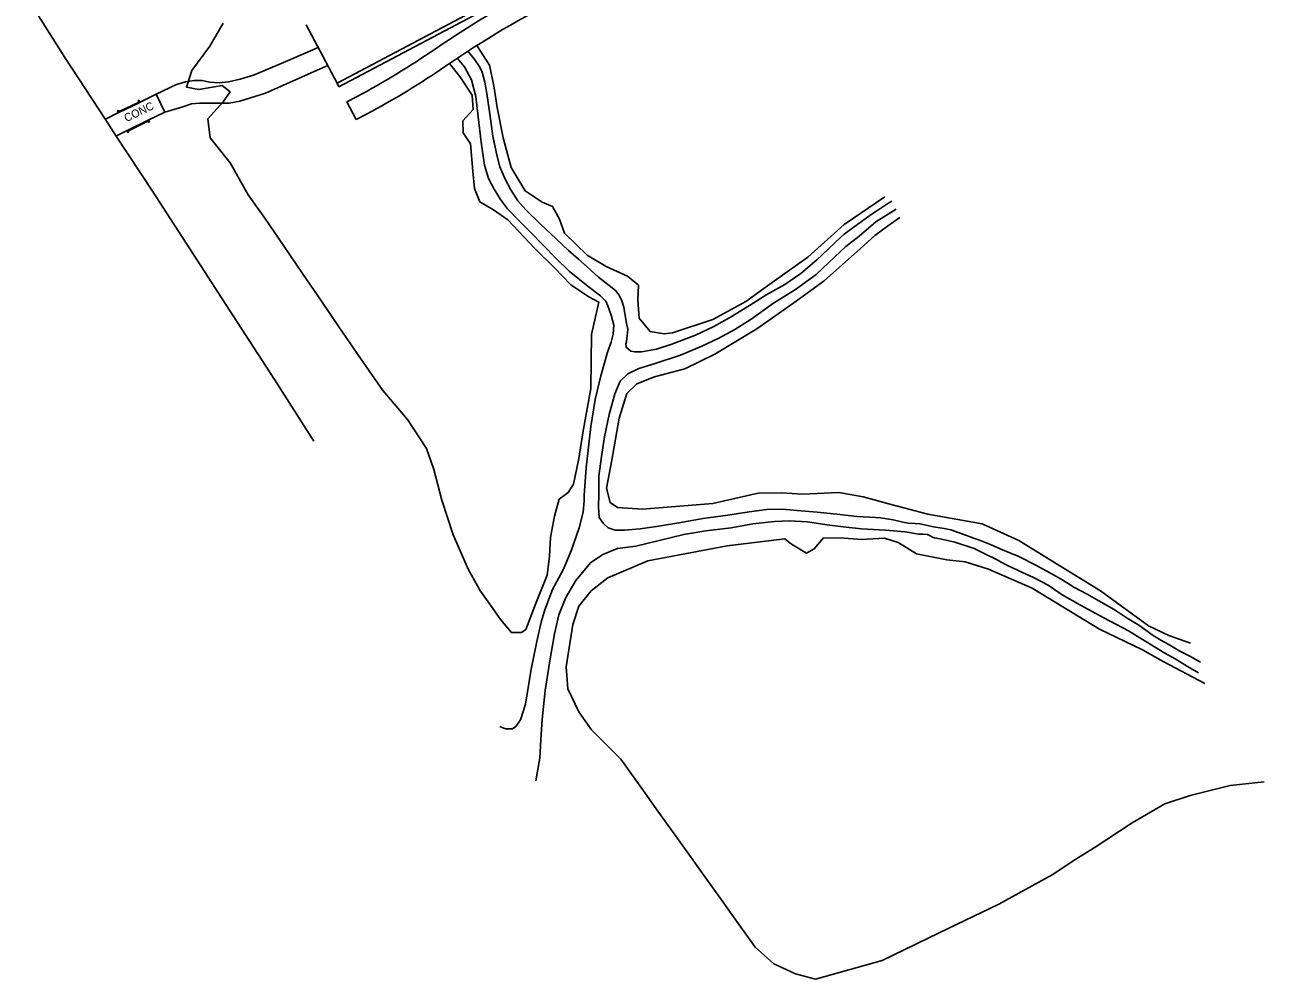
# Model space of a CAD drawing. Extents: x 1487693 to 1489338, y 497936 to 499734.
# Drawn here: x 1487693 to 1488313, y 497936 to 498412 of the extents above; entities that cross this region are included whole.
import ezdxf

# ---------------------------------------------------------------- set-up
doc = ezdxf.new("R2010")
doc.units = 0
for name, color, linetype in [('Exist Roads Curbs', 7, 'Continuous'), ('Exist Roads EOP', 7, 'Continuous'), ('Exist Roads EOP Other', 7, 'Continuous'), ('Exist Roads EOP Other Text', 7, 'Continuous'), ('Exist Roads Soil', 7, 'Continuous'), ('Exist Vegetation Woods Line', 7, 'Continuous'), ('Prop Conc 2ft 6in Curb and Gutter', 7, 'Continuous'), ('Prop Conc 4in Sidewalk', 7, 'Continuous'), ('Prop EOT', 7, 'Continuous')]:
    doc.layers.add(name, color=color, linetype=linetype)

msp = doc.modelspace()

# ---------------------------------------------------------------- linework, layer by layer
at = {"layer": 'Exist Roads Curbs'}
for points in [[(1487739.76, 498368.93), (1487740.04, 498369.54), (1487740.99, 498369.16), (1487750.11, 498373.59), (1487750.29, 498374.61), (1487750.83, 498374.37)], [(1487750.83, 498374.37), (1487750.59, 498373.38), (1487740.74, 498368.65), (1487739.76, 498368.93)], [(1487744.7, 498358.81), (1487745.13, 498359.75), (1487754.78, 498364.52), (1487755.85, 498364.17)], [(1487744.7, 498358.81), (1487745.23, 498358.62), (1487745.58, 498359.57), (1487754.62, 498363.96), (1487755.54, 498363.72), (1487755.85, 498364.17)]]:
    msp.add_lwpolyline(points, dxfattribs=at)
at = {"layer": 'Exist Roads EOP'}
for points in [[(1487693.5, 498427.87), (1487713.44, 498396.03), (1487733.84, 498365.05), (1487739.1, 498356.78), (1487757.33, 498329.19), (1487777.82, 498297.68)], [(1487759.21, 498377.68), (1487769.37, 498382.59), (1487773.83, 498383.92), (1487778.1, 498384.53), (1487781.97, 498384.53), (1487785.98, 498383.73), (1487790.67, 498383.41), (1487795.21, 498383.92), (1487801.16, 498385.18), (1487807.72, 498387.24), (1487820.37, 498392.44), (1487833.66, 498398.18), (1487840.07, 498401.02)], [(1487763.48, 498368.78), (1487772.46, 498371.42), (1487776.78, 498372.92), (1487780.8, 498373.14), (1487789.84, 498373.13), (1487795.58, 498373.12), (1487800.95, 498374.24), (1487813.75, 498378.14), (1487824.23, 498382.87), (1487838.14, 498388.98), (1487844.87, 498391.96)], [(1487777.82, 498297.68), (1487797.58, 498266.94), (1487818.25, 498235.23), (1487837.85, 498204.4)]]:
    msp.add_lwpolyline(points, dxfattribs=at)
at = {"layer": 'Exist Roads EOP Other'}
for points in [[(1487733.85, 498365.13), (1487740.73, 498368.64), (1487741.18, 498368.83), (1487750.54, 498373.36), (1487759.21, 498377.68), (1487763.48, 498368.78)], [(1487739.27, 498356.86), (1487744.95, 498359.66), (1487745.34, 498359.88), (1487754.86, 498364.57), (1487763.48, 498368.78)]]:
    msp.add_lwpolyline(points, dxfattribs=at)
at = {"layer": 'Exist Roads Soil'}
for points in [[(1487992.8, 498271.25), (1487991.79, 498274.42), (1487990.47, 498277.39), (1487988.71, 498279.71), (1487985.48, 498282.18), (1487980.22, 498286.24), (1487974.53, 498291.47), (1487970.09, 498295.27), (1487965.24, 498299.7), (1487958.99, 498305.49), (1487951.21, 498312.84), (1487943.9, 498319.95), (1487939.83, 498324.48), (1487936.37, 498329.99), (1487933.45, 498335.16), (1487930.78, 498341.35), (1487929.48, 498346.53), (1487927.32, 498356.65), (1487925.85, 498367.83), (1487924.38, 498377.95), (1487923.32, 498383.7), (1487922.02, 498388.61), (1487920.79, 498391.21), (1487918.11, 498395.39), (1487914.9, 498399.13)], [(1487981.4, 498237.08), (1487984.68, 498248.79), (1487986.53, 498253.92), (1487987.54, 498257.82), (1487987.79, 498262.28), (1487986.41, 498267.4), (1487984.8, 498272.03), (1487983.75, 498274.28), (1487981.23, 498276.93), (1487974.99, 498281.72), (1487965.45, 498289.32), (1487958.76, 498295.78), (1487952.42, 498302.4), (1487946.53, 498308.36), (1487940.29, 498314.61), (1487934.63, 498320.47), (1487931.21, 498325.07), (1487927.95, 498330.29), (1487925.23, 498335.58), (1487923.14, 498342.25), (1487921.46, 498353.8), (1487919.97, 498366.34), (1487918.8, 498376.58), (1487916.64, 498384.85), (1487913.27, 498391.29), (1487909.56, 498395.6)], [(1487998.13, 498248.94), (1488001.58, 498248.99), (1488009.14, 498250.29), (1488016.85, 498252.88), (1488028.57, 498257.26), (1488037.84, 498261.6), (1488046.16, 498266.36), (1488055.63, 498272.17), (1488064.34, 498277.72), (1488073.26, 498282.6), (1488081.19, 498288.09), (1488089.22, 498294.9), (1488094.75, 498300.05), (1488098.76, 498303.92), (1488102.94, 498307.7), (1488109.74, 498312.85), (1488115.28, 498316.73), (1488124.26, 498322.7), (1488126.64, 498324.22)], [(1488128.88, 498320.19), (1488118.78, 498313.96), (1488110.45, 498306.8), (1488103.79, 498301.57), (1488098.18, 498296.45), (1488088.95, 498287.56), (1488078.59, 498280.08), (1488067.61, 498273.26), (1488056.39, 498265.36), (1488048.22, 498260.11), (1488040.24, 498255.76), (1488031.77, 498251.78), (1488021.09, 498247.35), (1488008.48, 498243.18), (1488000.25, 498240.68), (1487994.75, 498238.1), (1487991.03, 498234.35), (1487988.26, 498228.05), (1487985.45, 498217.69), (1487983.17, 498206.59), (1487981.71, 498196.71), (1487980.28, 498186.98), (1487980.33, 498178.13), (1487980.09, 498171.36), (1487980.57, 498166.29), (1487982.53, 498163.44), (1487984.94, 498161.13), (1487988.49, 498159.91), (1487993.12, 498159.93), (1488000.97, 498160.56), (1488009.07, 498161.79), (1488020.32, 498163.6), (1488032.44, 498165.77), (1488044.75, 498167.41), (1488055.47, 498169.06), (1488064.34, 498170.27), (1488072.14, 498170.45), (1488079.38, 498169.79), (1488089.49, 498168.94), (1488099.18, 498168), (1488109.23, 498166.86), (1488115.53, 498166.46), (1488118.49, 498166.21), (1488121.02, 498166.1), (1488127.46, 498165.11), (1488132.18, 498164.02), (1488134.8, 498163.52), (1488138.41, 498163.27), (1488140.78, 498163.12), (1488147.6, 498161.61), (1488152.81, 498160.72), (1488156.15, 498160.1), (1488160.3, 498158.65), (1488165.94, 498156.63), (1488168.09, 498155.77), (1488170.57, 498154.9), (1488176.41, 498152.62), (1488182.09, 498150.21), (1488190.18, 498146.84), (1488198.63, 498142.47), (1488207.44, 498137.61), (1488212.24, 498135.04), (1488217.7, 498131.46), (1488224.25, 498128.05), (1488230.17, 498124.59), (1488237.75, 498120.28), (1488244.23, 498116.01), (1488248.54, 498113.48), (1488250.63, 498112.19), (1488257.33, 498107.35), (1488261.13, 498105.08), (1488264.84, 498102.98), (1488270.58, 498099.5), (1488275.24, 498097.13), (1488281, 498093.95)], [(1487998.13, 498248.94), (1487996.28, 498249.4), (1487993.94, 498251.33), (1487993.82, 498253.04), (1487994.13, 498254.17), (1487994.55, 498256.95), (1487994.74, 498260.33), (1487994.19, 498263.22), (1487992.8, 498271.25)], [(1487930.86, 498061.83), (1487933.61, 498060.75), (1487937.16, 498060.78), (1487938.89, 498061.96), (1487941.24, 498065.21), (1487943.61, 498073.08), (1487946.58, 498090.52), (1487949.33, 498104.43), (1487951.55, 498114.01), (1487953.34, 498120.24), (1487957.22, 498130.27), (1487962.55, 498140.15), (1487966.42, 498149.59), (1487970.53, 498161.2), (1487972.42, 498169), (1487972.97, 498174.6), (1487973.01, 498177.37), (1487974.01, 498191.07), (1487976.34, 498211.69), (1487978.41, 498225.2), (1487981.4, 498237.08)], [(1487948.87, 498034.82), (1487949.61, 498039.57), (1487950.84, 498046.04), (1487951.42, 498055.42), (1487951.96, 498065.46), (1487953.53, 498079.87), (1487955.89, 498094.73), (1487958.23, 498108.17), (1487960.34, 498117.7), (1487963.77, 498126.34), (1487968.76, 498134.78), (1487976.11, 498143.71), (1487982.38, 498147.83), (1487989.65, 498150.75), (1487998.84, 498151.97), (1488010.44, 498154.8), (1488022.73, 498157.84), (1488033.8, 498159.64), (1488046.43, 498161.09), (1488057.27, 498163.18), (1488068.04, 498164.33), (1488075.4, 498164.65), (1488084.57, 498164.05), (1488094.43, 498162.54), (1488102.43, 498161.54), (1488111.6, 498160.68), (1488123.53, 498159.95), (1488133.36, 498159.11), (1488140.16, 498157.92), (1488142.42, 498157.97), (1488144.51, 498157.84), (1488145.88, 498157.07), (1488147.04, 498156.43), (1488147.97, 498156.08), (1488150.88, 498155.57), (1488158.14, 498154.04), (1488167.8, 498150.79), (1488172.49, 498148.45), (1488179.28, 498145.18), (1488181.04, 498144.17), (1488184.56, 498142.27), (1488191.93, 498138.82), (1488197.52, 498136.38), (1488204.79, 498132.47), (1488211.83, 498127.58), (1488220.6, 498122.69), (1488232.62, 498116.24), (1488244.97, 498109.6), (1488255.87, 498103.09), (1488263.16, 498098.49), (1488268.33, 498095.62), (1488274.41, 498091.84), (1488279.89, 498088.74)]]:
    msp.add_lwpolyline(points, dxfattribs=at)
at = {"layer": 'Exist Vegetation Woods Line'}
for points in [[(1487901.91, 498174.88), (1487897.89, 498190.19), (1487894.27, 498200.69), (1487884.67, 498215.2), (1487872.46, 498229.66), (1487861.33, 498245.53), (1487850.43, 498261.53), (1487841.76, 498274.25), (1487832.26, 498288.2), (1487822.75, 498302.16), (1487813.44, 498315.79), (1487805.15, 498327.35), (1487796.18, 498343.46), (1487786.15, 498355.85), (1487784.88, 498365.4), (1487792.63, 498373.86), (1487796.12, 498378.84), (1487792.12, 498382.1), (1487780.51, 498379.99), (1487774.29, 498381.27), (1487777, 498389.55), (1487786.02, 498401.68), (1487792.65, 498413.13)], [(1488012.89, 498257.97), (1488005.93, 498259.21), (1488000.4, 498265.85), (1487999.82, 498274.82), (1488000.14, 498282.26), (1487994.59, 498286.82), (1487983.95, 498291.58), (1487974.47, 498297.26), (1487963.14, 498308.25), (1487960.7, 498315.2), (1487957.17, 498321.58), (1487951.96, 498323.77), (1487943.48, 498329.37), (1487936.5, 498341.09), (1487932.53, 498355.91), (1487929.58, 498371.03), (1487927.93, 498381.78), (1487925.76, 498392.12), (1487919.78, 498401.5), (1487919.33, 498401.97)], [(1487905.75, 498393.03), (1487910.89, 498386.56), (1487916.97, 498377.11), (1487917.48, 498370.09), (1487912.36, 498364.3), (1487912.53, 498358.4), (1487916.18, 498352.86), (1487917.31, 498339.19), (1487918.21, 498330.63), (1487920.83, 498323.84), (1487927.7, 498319.91), (1487934.78, 498314.96), (1487948.41, 498300.67), (1487958.36, 498290.72), (1487966.34, 498282.52), (1487975.28, 498276.55), (1487980.36, 498273.8), (1487976.6, 498257.73), (1487976.27, 498230.75)], [(1488123.2, 498326.49), (1488102.89, 498312.59), (1488084.8, 498296.33), (1488074.47, 498288.94), (1488065.81, 498282.75), (1488053.84, 498274.19), (1488037.28, 498265.08), (1488017.18, 498258.42), (1488012.89, 498257.97)], [(1488275.97, 498103.58), (1488265.18, 498107.43), (1488254.9, 498112.12), (1488230.98, 498129.66), (1488212.84, 498140.86), (1488190.24, 498154.82), (1488171.91, 498163.18), (1488144.63, 498167.94), (1488126.37, 498172.75), (1488112.33, 498176.56), (1488100.26, 498178.8), (1488082.16, 498177.98), (1488071.8, 498178.62), (1488059.9, 498178.41), (1488037.22, 498173.28), (1488002.21, 498170.44), (1487989.64, 498171.24), (1487985.98, 498173.75), (1487984.19, 498180.92), (1487986.87, 498194.92), (1487990.52, 498215.94), (1487994.24, 498228.22), (1487999.26, 498232.97), (1488008.06, 498236.51), (1488023.22, 498240.55), (1488038.36, 498247.88), (1488059.19, 498260.44), (1488077.68, 498273.55), (1488092.89, 498284.43), (1488111.02, 498300.67), (1488118.22, 498307.08), (1488124.48, 498311.7), (1488130.71, 498316.15)], [(1487976.27, 498230.75), (1487972.41, 498208.55), (1487970.25, 498195.74), (1487967.74, 498182.88), (1487964.98, 498178.69), (1487960.48, 498175.41), (1487958.15, 498166.88), (1487956.15, 498156.34), (1487955.66, 498146.95), (1487954.58, 498137.49), (1487948.97, 498123.82), (1487943.79, 498110.33), (1487941.74, 498108.87), (1487936.61, 498108.78), (1487931.25, 498115.42), (1487925.86, 498122.95), (1487921.26, 498129.56), (1487915.18, 498140.11), (1487907.59, 498157.63), (1487901.91, 498174.88)], [(1488312.78, 498034.19), (1488295.84, 498032.44), (1488275.81, 498027.43), (1488263.19, 498023.3), (1488246.84, 498013.77), (1488227.76, 498001.33), (1488218.59, 497995.7), (1488206.89, 497987.79), (1488180.25, 497973.22), (1488150.45, 497958.89), (1488121.84, 497945.03), (1488088.52, 497935.71), (1488078.67, 497938.33), (1488067.68, 497943.39), (1488058.49, 497951.7), (1488050.52, 497962.84), (1488041.93, 497974.86), (1488033.47, 497986.69), (1488023.11, 498001.18), (1488009.04, 498020.85), (1488003.47, 498028.65), (1487991.36, 498045.58), (1487976.72, 498060.32), (1487970.33, 498069.27), (1487964.8, 498080.74), (1487963.94, 498091.78), (1487967.27, 498112.89), (1487970.36, 498121.98), (1487976.5, 498129.65), (1487984.76, 498136.07), (1488004.78, 498144.58), (1488044.45, 498152.05), (1488073.33, 498155.62), (1488076.51, 498152.97), (1488084.03, 498148.41), (1488087.94, 498150.59), (1488092.59, 498156.06), (1488102.88, 498155.93), (1488111.51, 498155.34), (1488122.98, 498155.92), (1488129.91, 498153.77), (1488139.05, 498148.16), (1488154.21, 498145.16), (1488163.29, 498144.19), (1488175.03, 498140.53), (1488196.82, 498130.93), (1488230.56, 498110.43), (1488251.93, 498100.19), (1488262.37, 498094.4), (1488283.19, 498083.4)]]:
    msp.add_lwpolyline(points, dxfattribs=at)
at = {"layer": 'Prop Conc 2ft 6in Curb and Gutter'}
for p, q in [((1487850.46, 498381.4), (1488121.13, 498524.68)), ((1487849.52, 498383.17), (1487850.46, 498381.4))]:
    msp.add_line(p, q, dxfattribs=at)
at = {"layer": 'Prop Conc 4in Sidewalk'}
for p, q in [((1487854.44, 498373.89), (1487859.51, 498376.57)), ((1487859.11, 498365.05), (1487854.44, 498373.89)), ((1487859.11, 498365.05), (1487864.18, 498367.73))]:
    msp.add_line(p, q, dxfattribs=at)
for centre, radius, start, end in [((1488184.66, 497984.09), 505, 108.92779, 124.5146), ((1488184.66, 497984.09), 495, 108.92779, 124.5146), ((1487674.7, 498725.67), 395, 297.89497, 304.5146), ((1487674.7, 498725.67), 405, 297.89497, 304.5146)]:
    msp.add_arc(centre, radius, start, end, dxfattribs=at)
at = {"layer": 'Prop EOT'}
for q in [(1488120.19, 498526.45), (1487834.08, 498412.33)]:
    msp.add_line((1487849.52, 498383.17), q, dxfattribs=at)

# ---------------------------------------------------------------- texts
at = {"layer": 'Exist Roads EOP Other Text'}
msp.add_text('CONC', height=4, rotation=25.8066, dxfattribs=at).set_placement((1487744.27, 498363.66))

doc.saveas('drawing.dxf')
